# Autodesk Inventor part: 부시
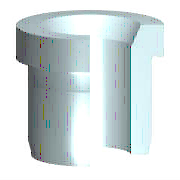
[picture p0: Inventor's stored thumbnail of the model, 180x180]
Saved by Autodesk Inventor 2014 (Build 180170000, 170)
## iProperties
IsCustomPart: 1
Created: 2009-02
Part Number: 부시
Material: 강, 연강
Description: 압력 맞춤 부시 - 머리 있는 유형
Document SubType Name: Modeling
Standard: ISO 4247
Designer: KYOUNG IL JANG
Standard Revision: 1판 1977-12-15
Standards Organization: ISO
Language: ko-KR
Size Designation: 15
Categories: <MemberInstance><Categories><Category DisplayName="기타 부품" InternalName="5aa15e00-363f-49f2-933f-16f664388e3f" Mnemonic="OTHER"><Category DisplayName="드릴 부싱" Int
Density: 7.86 g/cm^3
Appearance: 강철
Mass: 62.5871 g
Surface Area: 38.4072 cm^2
Volume: 7.96273 cm^3
Author: KYOUNG IL JANG
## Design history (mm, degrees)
revolve "본체" stored, may be unused: angle "d12" = 90 deg
body "Solid1"
chamfer "모따기1" distance "d13" = 2 (= KAH); stored, may be unused: angle "d14" = 30 deg (= SEWI), second distance "d19" = 2 (= KAH)
chamfer "모따기2" distance "d15" = 1.5 (= PHH); stored, may be unused: angle "d16" = 15 deg (= ANG), second distance "d20" = 1.5 (= PHH)
sketch "스케치1"
  geometry: L1 (2.5, 11)-(24, 11); L2 (24, 11)-(24, 6); L3 (24, 6)-(-4, 6); L4 (-4, 6)-(-4, 13); L5 (-4, 13)-(0, 13); L6 (0, 13)-(0, 12.304); L7 (-2.619, 0)-(24, 0); L8 (0, 12.304)-(-0.187, 11.425); L9 (2.5, 11)-(1.457, 10.72); L10 (0.4, 10.7)-(1.301, 10.7); L11 (-6.4, 0)-(10.4, 0) reference; L12 (0, -2.2)-(0, 13.2) reference; A1 r 0.6 centre (1.301, 11.3) between (1.301, 10.7) and (1.457, 10.72); A2 r 0.6 centre (0.4, 11.3) between (-0.187, 11.425) and (0.4, 10.7)
  constraints: 20 end point, 5 parallel, 4 point on circle, 4 tangent, 2 centre point, 2 collinear, 2 perpendicular, 1 horizontal, 1 point on line
  dimensions: "d0" = 15 deg angle of L1 L9; "d1" = 12 deg angle of L6 L8; "d2" = 0.6 radius of A2 (= FSRR); "d3" = 0.6 radius of A1 (= FSRR); "d4" = 0.3 distance between parallel lines of L1 L10 (= FST1); "d5" = 0.2 distance edge to line of A2 L6 (= FST2); "d6" = 2.5 distance from line of L1.start L6 (= FSB); "d7" = 12 diameter of L3 L7 (= NND); "d8" = 22 diameter of L1 L7 (= SD2); "d9" = 28 distance between parallel lines of L2 L4 (= NLG); "d10" = 4 distance of L4.end L5.end (= KOH); "d11" = 26 diameter of L5 L7 (= KOD)
other parameters: "NLG" = 28 [user parameter; used in 1 equation term], "NND" = 12 [user parameter; used in 1 equation term], "KOH" = 4 [user parameter; used in 1 equation term], "KOD" = 26 [user parameter; used in 1 equation term], "KAH" = 2 [user parameter; used in 2 equation terms], "SEWI" = 30 deg [user parameter; used in 1 equation term], "ANG" = 15 deg [user parameter; used in 1 equation term], "PHH" = 1.5 [user parameter; used in 2 equation terms], "FST1" = 0.3 [user parameter; used in 1 equation term], "FST2" = 0.2 [user parameter; used in 1 equation term], "FSB" = 2.5 [user parameter; used in 1 equation term], "FSRR" = 0.6 [user parameter; used in 2 equation terms], "SD2" = 22 [user parameter; used in 1 equation term], "d17" = 0, "d18" = 0, "NNDMIN" = 12 [user parameter], "FSH" = 2.1 [user parameter], "NNDMAX" = 15 [user parameter]
